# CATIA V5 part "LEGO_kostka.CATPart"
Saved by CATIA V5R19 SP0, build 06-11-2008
Part number: LEGO_v3.1
Source: Unknown
Bounding box of the stored display mesh (mm): x -31.42 to 32.194, y -46.664 to 0, z 0 to 10.351
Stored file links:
  C:\Users\jsmid\Desktop\DP_Smidak_Forma LEGO\LEGO_kostka.CATPart
  Product2.CATProduct
  C:\Users\jsmid\Desktop\Forma_kostka\Product3.CATProduct
  C:\Users\jsmid\Desktop\LEGO_tvarnik.CATPart
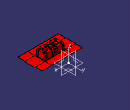
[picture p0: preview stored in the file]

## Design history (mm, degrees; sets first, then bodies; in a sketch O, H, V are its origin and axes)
Parameters
  DraftAngle = 0 deg
  Tesselation1 = 0.01 mm
  Tesselation2 = -1 mm
  `Compute Mode` = 0
  ValExplode = 10 mm
  Stroke = 0 mm
  `Stroke Angle` = 0 deg
AxisSystem1 "Main Pulling Direction.1": origin (0, 0, 0), X (1, 0, 0), Y (0, 1, 0), Z (0, 0, 1)
Set1 "Core.1"
  DatumSurface1
  DatumSurface2 "TrfSurface.27"
  DatumSurface3 "TrfSurface.28"
  DatumSurface4 "TrfSurface.29"
  DatumSurface5 "TrfSurface.30"
  DatumSurface6 "TrfSurface.31"
  DatumSurface7 "TrfSurface.32"
  DatumSurface8 "TrfSurface.33"
  DatumSurface9 "TrfSurface.34"
  DatumSurface10 "TrfSurface.35"
  DatumSurface11 "TrfSurface.36"
  DatumSurface12 "TrfSurface.37"
  DatumSurface13 "TrfSurface.38"
  DatumSurface14 "TrfSurface.39"
  DatumSurface15 "TrfSurface.40"
  DatumSurface16 "TrfSurface.41"
  DatumSurface17 "TrfSurface.42"
  DatumSurface18 "TrfSurface.43"
  DatumSurface19 "TrfSurface.44"
  DatumSurface20 "TrfSurface.45"
  DatumSurface21 "TrfSurface.46"
  DatumSurface22 "TrfSurface.47"
  DatumSurface23 "TrfSurface.48"
  DatumSurface24 "TrfSurface.49"
  DatumSurface25 "TrfSurface.50"
  DatumSurface26 "TrfSurface.51"
  DatumSurface27 "TrfSurface.52"
  DatumSurface28 "TrfSurface.53"
  DatumSurface29 "TrfSurface.54"
  DatumSurface30 "TrfSurface.55"
  DatumSurface31 "TrfSurface.56"
  DatumSurface32 "TrfSurface.57"
  DatumSurface33 "TrfSurface.58"
  Join1: Elements (DatumSurface1; DatumSurface2; DatumSurface3; DatumSurface4; DatumSurface5; DatumSurface6; DatumSurface7; DatumSurface8; DatumSurface9; DatumSurface10; DatumSurface11; DatumSurface12; DatumSurface13; DatumSurface14; DatumSurface15; DatumSurface16; DatumSurface17; DatumSurface18; DatumSurface19; DatumSurface20; DatumSurface21; DatumSurface22; DatumSurface23; DatumSurface24; DatumSurface25; DatumSurface26; DatumSurface27; DatumSurface28; DatumSurface29; DatumSurface30; DatumSurface31; DatumSurface32; DatumSurface33)
Set2 "Cavity.1"
  DatumSurface34
  DatumSurface35 "TrfSurface.59"
  DatumSurface36 "TrfSurface.60"
  DatumSurface37 "TrfSurface.61"
  DatumSurface38 "TrfSurface.62"
  DatumSurface39 "TrfSurface.63"
  DatumSurface40 "TrfSurface.64"
  DatumSurface41 "TrfSurface.65"
  DatumSurface42 "TrfSurface.66"
  Join2: Elements (DatumSurface34; DatumSurface35; DatumSurface36; DatumSurface37; DatumSurface38; DatumSurface39; DatumSurface40; DatumSurface41; DatumSurface42)
Set3 "help"
  Sketch1 on face of DatumSurface1, origin (0, 0, 0), H (1, 0, 0), V (0, 1, 0)
    point P1 (0, -27.939)
    line L1 (30.9795, -4.9995) -> (30.9795, -50.8785)
    line L2 (30.9795, -50.8785) -> (-30.9795, -50.8785)
    line L3 (-30.9795, -50.8785) -> (-30.9795, -4.9995)
    line L4 (-30.9795, -4.9995) -> (30.9795, -4.9995)
    reference projected line E1 (15.9795, -19.9995) -> (-15.9795, -19.9995) from edge of DatumSurface34
    reference projected line E2 (-15.9795, -35.8785) -> (15.9795, -35.8785) from edge of Extrude2
    reference projected line E3 (15.9795, -35.8785) -> (15.9795, -19.9995) from edge of Extrude1
    reference projected line E4 (-15.9795, -19.9995) -> (-15.9795, -35.8785) from edge of Extrude4
    distance E1 L4 = 15
    distance E2 L2 = 15
    distance E3 L1 = 15
    distance E4 L3 = 15
    vertical: L1 V, L3 V
    horizontal: L2 H, L4 H
    equidistance: L1 L3 P1, L2 L4 P1
  Boundary1 "PrtSrf_Boundary.1": Boundary DatumSurface34, BoundaryTo vertex [face of DatumSurface34 | face of DatumSurface34], BoundaryFrom vertex [face of DatumSurface34 | face of DatumSurface34]
  Extrude1 "PrtSrf_Extrude.1": Limit1 16.2142, Limit2 0, Element1 CurveSmooth1, Direction (1000, 0, 0)
  CurveSmooth1 "PrtSrf_Curve smooth.1": CurveToSmooth Boundary1
  Boundary2 "PrtSrf_Boundary.2": Boundary DatumSurface34, BoundaryTo vertex [face of DatumSurface34 | face of DatumSurface34], BoundaryFrom vertex [face of DatumSurface34 | face of DatumSurface34]
  Extrude2 "PrtSrf_Extrude.2": Limit1 10.7853, Limit2 0, Element1 CurveSmooth2, Direction (0, -1000, 0)
  CurveSmooth2 "PrtSrf_Curve smooth.2": CurveToSmooth Boundary2
  Boundary3 "PrtSrf_Boundary.3": Boundary DatumSurface34, BoundaryTo vertex [face of DatumSurface34 | face of DatumSurface34], BoundaryFrom vertex [face of DatumSurface34 | face of DatumSurface34]
  Extrude3 "PrtSrf_Extrude.3": Limit1 10.245, Limit2 0, Element1 CurveSmooth3, Direction (0, 1000, 0)
  CurveSmooth3 "PrtSrf_Curve smooth.3": CurveToSmooth Boundary3
  Boundary4 "PrtSrf_Boundary.4": Boundary DatumSurface34, BoundaryTo vertex [face of DatumSurface34 | face of DatumSurface34], BoundaryFrom vertex [face of DatumSurface34 | face of DatumSurface34]
  Extrude4 "PrtSrf_Extrude.4": Limit1 15.4406, Limit2 0, Element1 CurveSmooth4, Direction (-1000, 0, 0)
  CurveSmooth4 "PrtSrf_Curve smooth.4": CurveToSmooth Boundary4
  Join3 "PrtSrf_Join.1": Elements (Extrude1; Extrude2; Extrude3; Extrude4)
  Extrude5: Lim1 15, Lim2 0, Element1 edge of Extrude3, Direction (1, 0, 0)
  Extrude6: Lim1 15, Lim2 0, Element1 edge of Extrude2, Direction (1, 0, 0)
  Extrude7: Lim1 15, Lim2 0, Element1 edge of Extrude3, Direction (1, 0, 0)
  Extrude8: Lim1 15, Lim2 0, Element1 edge of Extrude2, Direction (1, 0, 0)
Body1 "Body.4" (main body)
  Solid1: solid without history
  Sketch2 on yz-plane, origin (0, 0, 0), H (0, 1, 0), V (0, 0, 1)
    line L1 (7.9395, 0) -> (7.7505, 10.8275)
    reference projected line E1 (7.7711, 9.648) -> (7.9395, 0) from edge [face of Solid1 | face of Solid1]
    line L2 (7.7505, 10.8275) -> (10.6989, 34.6607)
    line L3 (10.6989, 34.6607) -> (19.9314, 34.6607)
    line L4 (19.9314, 34.6607) -> (22.9028, 15.7223)
    line L5 (22.9028, 15.7223) -> (47.6291, 15.7223)
    line L6 (47.6291, 15.7223) -> (39.4578, -8.8551)
    line L7 (39.4578, -8.8551) -> (4.2255, -8.8551)
    line L8 (4.2255, -8.8551) -> (4.2255, 0)
    line L9 (4.2255, 0) -> (7.9395, 0)
    reference projected line E2 (7.9395, 0) -> (-7.9395, 0) from edge [face of Solid1 | face of Solid1]
    point P10 (10.1426, 0)
    coincidence: L1 E1, L9 E2
    horizontal: L3 H, L5 H, L7 H, L9 H
    vertical: L8 V
  Pocket1: profile Sketch2, direction (1, 0, 0), length 33, mirrored extent
  Translate1: Length -27.939, Direction (0, 1, 0), ToTransfor Pocket1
